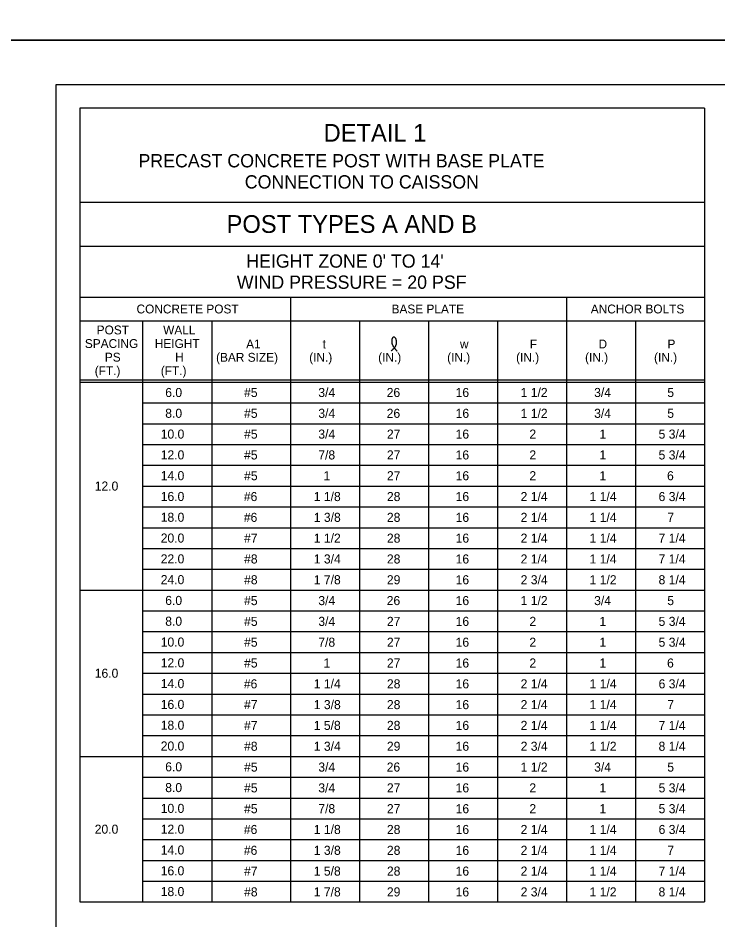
# Model space of a CAD drawing. Extents: x 3351 to 8430, y -3586 to 1457.
# Drawn here: x 4629.5 to 4866.3, y -320.1 to -14.8 of the extents above; entities that cross this region are included whole.
import ezdxf

# ---------------------------------------------------------------- set-up
doc = ezdxf.new("R2010")
doc.units = 0
for name, color, linetype in [('1', 7, 'Continuous'), ('2', 7, 'Continuous'), ('PLT-BNDY', 7, 'Continuous')]:
    doc.layers.add(name, color=color, linetype=linetype)

msp = doc.modelspace()

# ---------------------------------------------------------------- linework, layer by layer
at = {"layer": '1'}
for p, q in [((4650.34, -45.31), (4650.34, -314.06)), ((4861.68, -45.31), (4650.34, -45.31)), ((4861.68, -45.31), (4861.68, -314.06)), ((4861.68, -77.31), (4650.34, -77.31)), ((4650.34, -92.01), (4861.68, -92.01)), ((4650.34, -109.31), (4861.68, -109.31)), ((4650.34, -109.31), (4718.34, -109.31)), ((4721.68, -109.31), (4721.68, -314.06)), ((4815.01, -109.31), (4815.01, -314.06)), ((4650.34, -117.31), (4861.68, -117.31)), ((4671.68, -314.06), (4671.68, -117.31)), ((4695.01, -117.31), (4695.01, -314.06)), ((4745.01, -117.31), (4745.01, -314.06)), ((4768.34, -117.31), (4768.34, -314.06)), ((4791.68, -117.31), (4791.68, -314.06)), ((4838.34, -117.31), (4838.34, -314.06)), ((4650.34, -137.31), (4861.68, -137.31)), ((4650.34, -138.06), (4861.68, -138.06)), ((4708.34, -141.58), (4708.34, -141.58)), ((4733.34, -141.58), (4733.34, -141.58)), ((4756.68, -141.58), (4756.68, -141.58)), ((4780.01, -141.58), (4780.01, -141.58)), ((4803.34, -141.58), (4803.34, -141.58)), ((4826.68, -141.58), (4826.68, -141.58)), ((4850.01, -141.58), (4850.01, -141.58)), ((4671.68, -145.1), (4861.68, -145.1)), ((4671.68, -152.14), (4861.68, -152.14)), ((4671.68, -159.18), (4861.68, -159.18)), ((4671.68, -166.22), (4861.68, -166.22)), ((4671.68, -173.26), (4861.68, -173.26)), ((4671.68, -180.3), (4861.68, -180.3)), ((4671.68, -187.34), (4861.68, -187.34)), ((4671.68, -194.38), (4861.68, -194.38)), ((4671.68, -201.42), (4861.68, -201.42)), ((4650.34, -208.46), (4861.68, -208.46)), ((4708.34, -211.98), (4708.34, -211.98)), ((4733.34, -211.98), (4733.34, -211.98)), ((4756.68, -211.98), (4756.68, -211.98)), ((4780.01, -211.98), (4780.01, -211.98)), ((4803.34, -211.98), (4803.34, -211.98)), ((4826.68, -211.98), (4826.68, -211.98)), ((4850.01, -211.98), (4850.01, -211.98)), ((4671.68, -215.5), (4861.68, -215.5)), ((4671.68, -222.54), (4861.68, -222.54)), ((4671.68, -229.58), (4861.68, -229.58)), ((4671.68, -236.62), (4861.68, -236.62)), ((4671.68, -243.66), (4861.68, -243.66)), ((4671.68, -250.7), (4861.68, -250.7)), ((4671.68, -257.74), (4861.68, -257.74)), ((4650.34, -264.78), (4861.68, -264.78)), ((4708.34, -268.3), (4708.34, -268.3)), ((4733.34, -268.3), (4733.34, -268.3)), ((4756.68, -268.3), (4756.68, -268.3)), ((4780.01, -268.3), (4780.01, -268.3)), ((4803.34, -268.3), (4803.34, -268.3)), ((4826.68, -268.3), (4826.68, -268.3)), ((4850.01, -268.3), (4850.01, -268.3)), ((4671.68, -271.82), (4861.68, -271.82)), ((4671.68, -271.82), (4861.68, -271.82)), ((4671.68, -278.86), (4861.68, -278.86)), ((4671.68, -285.9), (4861.68, -285.9)), ((4671.68, -292.94), (4861.68, -292.94)), ((4671.68, -299.98), (4861.68, -299.98)), ((4671.68, -307.02), (4861.68, -307.02)), ((4650.34, -314.06), (4861.68, -314.06))]:
    msp.add_line(p, q, dxfattribs=at)
msp.add_spline([(4755.73, -127.48), (4755.94, -127.31), (4756.06, -127.18), (4756.26, -126.98), (4756.42, -126.82), (4756.7, -126.61), (4756.9, -126.35), (4757.08, -126.16), (4757.2, -125.93), (4757.3, -125.68), (4757.38, -125.44), (4757.46, -125.21), (4757.49, -125.02), (4757.52, -124.77), (4757.54, -124.55), (4757.52, -124.3), (4757.48, -124.05), (4757.43, -123.81), (4757.37, -123.58), (4757.28, -123.35), (4757.21, -123.22), (4757.11, -123.12), (4757.02, -123.02), (4756.92, -122.94), (4756.81, -122.88), (4756.72, -122.85), (4756.56, -122.85), (4756.46, -122.88), (4756.31, -122.93), (4756.22, -123.01), (4756.16, -123.1), (4756.09, -123.22), (4756.02, -123.33), (4755.98, -123.47), (4755.95, -123.58), (4755.91, -123.82), (4755.89, -123.99), (4755.91, -124.18), (4755.91, -124.38), (4755.95, -124.66), (4755.97, -124.89), (4756.01, -125.06), (4756.08, -125.28), (4756.18, -125.5), (4756.28, -125.7), (4756.37, -125.9), (4756.49, -126.12), (4756.69, -126.3), (4756.81, -126.51), (4756.94, -126.67), (4757.05, -126.85), (4757.2, -127.02), (4757.33, -127.19), (4757.44, -127.3), (4757.55, -127.43), (4757.66, -127.6)], degree=3, dxfattribs=at)
at = {"layer": '2'}
for p, q in [((4642.34, -601.31), (4642.34, -37.31)), ((4642.34, -37.31), (5428.34, -37.31))]:
    msp.add_line(p, q, dxfattribs=at)
at = {"layer": 'PLT-BNDY'}
for points in [[(4602.34, 571.69), (5443.34, 571.69), (5443.34, -22.31), (4602.34, -22.31)], [(4602.34, -22.31), (5443.34, -22.31), (5443.34, -616.31), (4602.34, -616.31)]]:
    msp.add_lwpolyline(points, close=True, dxfattribs=at)

# ---------------------------------------------------------------- texts
at = {"layer": '1'}
for s, height, p in [('DETAIL 1', 6, (4732.84, -56.66)), ('PRECAST CONCRETE POST WITH BASE PLATE', 4.5, (4670.19, -65.36)), ('CONNECTION TO CAISSON', 4.5, (4706.17, -72.52)), ('POST TYPES A AND B', 6, (4700.01, -87.54)), ("HEIGHT ZONE 0' TO 14'", 4.5, (4706.66, -99.32)), ('WIND PRESSURE = 20 PSF', 4.5, (4703.47, -106.48)), ('CONCRETE POST', 3, (4669.55, -114.81)), ('BASE PLATE', 3, (4755.84, -114.81)), ('ANCHOR BOLTS', 3, (4823.24, -114.81)), ('POST', 3, (4656.07, -121.91)), ('WALL', 3, (4678.56, -121.91)), ('SPACING', 3, (4652.07, -126.51)), ('HEIGHT', 3, (4675.73, -126.51)), ('A1', 3, (4706.64, -126.67)), ('t', 3, (4732.51, -126.67)), ('w', 3, (4778.99, -126.67)), ('F', 3, (4802.6, -126.67)), ('D', 3, (4825.87, -126.67)), ('P', 3, (4849.2, -126.67)), ('PS', 3, (4658.83, -131.11)), ('H', 3, (4682.61, -131.11)), ('(BAR SIZE)', 3, (4696.47, -131.17)), ('(IN.)', 3, (4727.98, -131.17)), ('(IN.)', 3, (4751.31, -131.17)), ('(IN.)', 3, (4774.65, -131.17)), ('(IN.)', 3, (4797.98, -131.17)), ('(IN.)', 3, (4821.31, -131.17)), ('(IN.)', 3, (4844.65, -131.17)), ('(FT.)', 3, (4655.4, -135.71)), ('(FT.)', 3, (4677.76, -135.71)), ('6.0', 3.07, (4679.26, -143.11)), ('#5', 3.07, (4705.94, -143.11)), ('3/4', 3.07, (4731.06, -143.11)), ('26', 3.07, (4754.19, -143.11)), ('16', 3.07, (4777.52, -143.11)), ('1 1/2', 3.07, (4799.51, -143.11)), ('3/4', 3.07, (4824.39, -143.11)), ('5', 3.07, (4849.14, -143.11)), ('8.0', 3.07, (4679.26, -150.15)), ('#5', 3.07, (4705.94, -150.16)), ('3/4', 3.07, (4731.06, -150.16)), ('26', 3.07, (4754.19, -150.16)), ('16', 3.07, (4777.52, -150.16)), ('1 1/2', 3.07, (4799.51, -150.16)), ('3/4', 3.07, (4824.39, -150.16)), ('5', 3.07, (4849.14, -150.16)), ('10.0', 3.07, (4677.73, -157.19)), ('#5', 3.07, (4705.94, -157.2)), ('3/4', 3.07, (4731.06, -157.2)), ('27', 3.07, (4754.27, -157.2)), ('16', 3.07, (4777.52, -157.2)), ('2', 3.07, (4802.47, -157.2)), ('1', 3.07, (4826.16, -157.2)), ('5 3/4', 3.07, (4846.19, -157.2)), ('12.0', 3.07, (4677.73, -164.23)), ('#5', 3.07, (4705.94, -164.25)), ('7/8', 3.07, (4731.05, -164.25)), ('27', 3.07, (4754.27, -164.25)), ('16', 3.07, (4777.52, -164.25)), ('2', 3.07, (4802.47, -164.25)), ('1', 3.07, (4826.16, -164.25)), ('5 3/4', 3.07, (4846.19, -164.25)), ('14.0', 3.07, (4677.73, -171.27)), ('#5', 3.07, (4705.94, -171.29)), ('1', 3.07, (4732.82, -171.29)), ('27', 3.07, (4754.27, -171.29)), ('16', 3.07, (4777.52, -171.29)), ('2', 3.07, (4802.47, -171.29)), ('1', 3.07, (4826.16, -171.29)), ('6', 3.07, (4849.05, -171.29)), ('12.0', 3.07, (4655.4, -174.79)), ('16.0', 3.07, (4677.73, -178.31)), ('#6', 3.07, (4705.85, -178.34)), ('1 1/8', 3.07, (4729.51, -178.34)), ('28', 3.07, (4754.27, -178.34)), ('16', 3.07, (4777.52, -178.34)), ('2 1/4', 3.07, (4799.51, -178.34)), ('1 1/4', 3.07, (4822.84, -178.34)), ('6 3/4', 3.07, (4846.19, -178.34)), ('18.0', 3.07, (4677.73, -185.35)), ('#6', 3.07, (4705.85, -185.38)), ('1 3/8', 3.07, (4729.52, -185.38)), ('28', 3.07, (4754.27, -185.38)), ('16', 3.07, (4777.52, -185.38)), ('2 1/4', 3.07, (4799.51, -185.38)), ('1 1/4', 3.07, (4822.84, -185.38)), ('7', 3.07, (4849.14, -185.38)), ('20.0', 3.07, (4677.73, -192.39)), ('1 1/2', 3.07, (4729.51, -192.42)), ('28', 3.07, (4754.27, -192.42)), ('16', 3.07, (4777.52, -192.42)), ('2 1/4', 3.07, (4799.51, -192.42)), ('1 1/4', 3.07, (4822.84, -192.42)), ('7 1/4', 3.07, (4846.18, -192.42)), ('#7', 3.07, (4705.94, -192.42)), ('22.0', 3.07, (4677.73, -199.43)), ('#8', 3.07, (4705.94, -199.47)), ('1 3/4', 3.07, (4729.52, -199.47)), ('28', 3.07, (4754.27, -199.47)), ('16', 3.07, (4777.52, -199.47)), ('2 1/4', 3.07, (4799.51, -199.47)), ('1 1/4', 3.07, (4822.84, -199.47)), ('7 1/4', 3.07, (4846.18, -199.47)), ('24.0', 3.07, (4677.73, -206.47)), ('#8', 3.07, (4705.94, -206.51)), ('1 7/8', 3.07, (4729.51, -206.51)), ('29', 3.07, (4754.26, -206.51)), ('16', 3.07, (4777.52, -206.51)), ('2 3/4', 3.07, (4799.52, -206.51)), ('1 1/2', 3.07, (4822.84, -206.51)), ('8 1/4', 3.07, (4846.18, -206.51)), ('6.0', 3.07, (4679.26, -213.51)), ('#5', 3.07, (4705.94, -213.56)), ('3/4', 3.07, (4731.06, -213.56)), ('26', 3.07, (4754.19, -213.56)), ('16', 3.07, (4777.52, -213.56)), ('1 1/2', 3.07, (4799.51, -213.56)), ('3/4', 3.07, (4824.39, -213.56)), ('5', 3.07, (4849.14, -213.56)), ('8.0', 3.07, (4679.26, -220.55)), ('#5', 3.07, (4705.94, -220.6)), ('3/4', 3.07, (4731.06, -220.6)), ('27', 3.07, (4754.27, -220.6)), ('16', 3.07, (4777.52, -220.6)), ('2', 3.07, (4802.47, -220.6)), ('1', 3.07, (4826.16, -220.6)), ('5 3/4', 3.07, (4846.19, -220.6)), ('10.0', 3.07, (4677.73, -227.59)), ('#5', 3.07, (4705.94, -227.65)), ('7/8', 3.07, (4731.05, -227.65)), ('27', 3.07, (4754.27, -227.65)), ('16', 3.07, (4777.52, -227.65)), ('2', 3.07, (4802.47, -227.65)), ('1', 3.07, (4826.16, -227.65)), ('5 3/4', 3.07, (4846.19, -227.65)), ('12.0', 3.07, (4677.73, -234.63)), ('#5', 3.07, (4705.94, -234.69)), ('1', 3.07, (4732.82, -234.69)), ('27', 3.07, (4754.27, -234.69)), ('16', 3.07, (4777.52, -234.69)), ('2', 3.07, (4802.47, -234.69)), ('1', 3.07, (4826.16, -234.69)), ('6', 3.07, (4849.05, -234.69)), ('16.0', 3.07, (4655.4, -238.15)), ('14.0', 3.07, (4677.73, -241.67)), ('#6', 3.07, (4705.85, -241.74)), ('1 1/4', 3.07, (4729.51, -241.74)), ('28', 3.07, (4754.27, -241.74)), ('16', 3.07, (4777.52, -241.74)), ('2 1/4', 3.07, (4799.51, -241.74)), ('1 1/4', 3.07, (4822.84, -241.74)), ('6 3/4', 3.07, (4846.19, -241.74)), ('16.0', 3.07, (4677.73, -248.71)), ('#7', 3.07, (4705.94, -248.78)), ('1 3/8', 3.07, (4729.52, -248.78)), ('28', 3.07, (4754.27, -248.78)), ('16', 3.07, (4777.52, -248.78)), ('2 1/4', 3.07, (4799.51, -248.78)), ('1 1/4', 3.07, (4822.84, -248.78)), ('7', 3.07, (4849.14, -248.78)), ('18.0', 3.07, (4677.73, -255.75)), ('#7', 3.07, (4705.94, -255.82)), ('1 5/8', 3.07, (4729.5, -255.82)), ('28', 3.07, (4754.27, -255.82)), ('16', 3.07, (4777.52, -255.82)), ('2 1/4', 3.07, (4799.51, -255.82)), ('1 1/4', 3.07, (4822.84, -255.82)), ('7 1/4', 3.07, (4846.18, -255.82)), ('20.0', 3.07, (4677.73, -262.79)), ('#8', 3.07, (4705.94, -262.87)), ('1 3/4', 3.07, (4729.52, -262.87)), ('29', 3.07, (4754.26, -262.87)), ('16', 3.07, (4777.52, -262.87)), ('2 3/4', 3.07, (4799.52, -262.87)), ('1 1/2', 3.07, (4822.84, -262.87)), ('8 1/4', 3.07, (4846.18, -262.87)), ('6.0', 3.07, (4679.26, -269.83)), ('#5', 3.07, (4705.94, -269.92)), ('3/4', 3.07, (4731.06, -269.92)), ('26', 3.07, (4754.19, -269.92)), ('16', 3.07, (4777.52, -269.92)), ('1 1/2', 3.07, (4799.51, -269.92)), ('3/4', 3.07, (4824.39, -269.92)), ('5', 3.07, (4849.14, -269.92)), ('8.0', 3.07, (4679.26, -276.87)), ('#5', 3.07, (4705.94, -276.96)), ('3/4', 3.07, (4731.06, -276.96)), ('27', 3.07, (4754.27, -276.96)), ('16', 3.07, (4777.52, -276.96)), ('2', 3.07, (4802.47, -276.96)), ('1', 3.07, (4826.16, -276.96)), ('5 3/4', 3.07, (4846.19, -276.96)), ('10.0', 3.07, (4677.73, -283.91)), ('7/8', 3.07, (4731.05, -284.01)), ('27', 3.07, (4754.27, -284.01)), ('16', 3.07, (4777.52, -284.01)), ('2', 3.07, (4802.47, -284.01)), ('5 3/4', 3.07, (4846.19, -284.01)), ('#5', 3.07, (4705.94, -284.01)), ('1', 3.07, (4826.16, -284.01)), ('20.0', 3.07, (4655.4, -290.95)), ('12.0', 3.07, (4677.73, -290.95)), ('#6', 3.07, (4705.85, -291.05)), ('1 1/8', 3.07, (4729.51, -291.05)), ('28', 3.07, (4754.27, -291.05)), ('16', 3.07, (4777.52, -291.05)), ('2 1/4', 3.07, (4799.51, -291.05)), ('1 1/4', 3.07, (4822.84, -291.05)), ('6 3/4', 3.07, (4846.19, -291.05)), ('14.0', 3.07, (4677.73, -297.99)), ('#6', 3.07, (4705.85, -298.1)), ('1 3/8', 3.07, (4729.52, -298.1)), ('28', 3.07, (4754.27, -298.1)), ('16', 3.07, (4777.52, -298.1)), ('2 1/4', 3.07, (4799.51, -298.1)), ('1 1/4', 3.07, (4822.84, -298.1)), ('7', 3.07, (4849.14, -298.1)), ('16.0', 3.07, (4677.73, -305.03)), ('#7', 3.07, (4705.94, -305.14)), ('1 5/8', 3.07, (4729.5, -305.14)), ('28', 3.07, (4754.27, -305.14)), ('16', 3.07, (4777.52, -305.14)), ('2 1/4', 3.07, (4799.51, -305.14)), ('1 1/4', 3.07, (4822.84, -305.14)), ('7 1/4', 3.07, (4846.18, -305.14)), ('18.0', 3.07, (4677.73, -312.07)), ('#8', 3.07, (4705.94, -312.18)), ('1 7/8', 3.07, (4729.51, -312.18)), ('29', 3.07, (4754.26, -312.18)), ('16', 3.07, (4777.52, -312.18)), ('2 3/4', 3.07, (4799.52, -312.18)), ('1 1/2', 3.07, (4822.84, -312.18)), ('8 1/4', 3.07, (4846.18, -312.18))]:
    msp.add_text(s, height=height, dxfattribs=at).set_placement(p)

doc.saveas('drawing.dxf')
